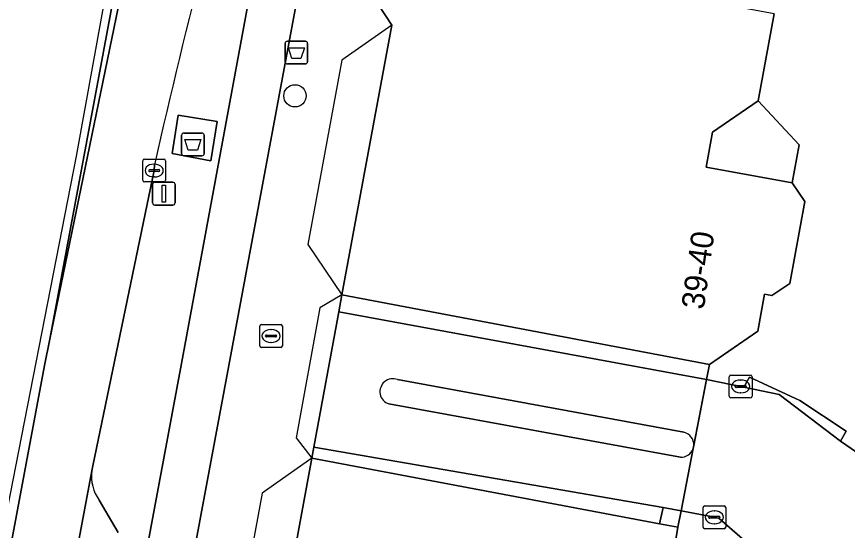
# Model space of a CAD drawing. Extents: x 161838 to 162344, y 381620 to 382160.
# Drawn here: x 161914.31 to 161950.8, y 382018.7 to 382041.26 of the extents above; entities that cross this region are included whole.
import ezdxf

# ---------------------------------------------------------------- set-up
doc = ezdxf.new("R2010")
doc.units = 0
for name, color, linetype in [('IMGEO_Afval_apart_plaats', 7, 'Continuous'), ('IMGEO_Afvalbak', 7, 'Continuous'), ('IMGEO_Berm_open', 7, 'Continuous'), ('IMGEO_Boom', 7, 'Continuous'), ('IMGEO_Brandkraan', 7, 'Continuous'), ('IMGEO_Fietspad_gesloten', 7, 'Continuous'), ('IMGEO_Kolk', 7, 'Continuous'), ('IMGEO_Lichtmast', 7, 'Continuous'), ('IMGEO_OVBaan_gesloten', 7, 'Continuous'), ('IMGEO_Pand', 7, 'Continuous'), ('IMGEO_Pand_nummerreeks', 7, 'Continuous'), ('IMGEO_Pand_overbouw', 7, 'Continuous'), ('IMGEO_Parkeervlak_open', 7, 'Continuous'), ('IMGEO_Rijbaan_lokaal_gesloten', 7, 'Continuous'), ('IMGEO_Rijbaan_lokaal_open', 7, 'Continuous'), ('IMGEO_Verkeerseiland_open', 7, 'Continuous'), ('IMGEO_Voetpad_gesloten', 7, 'Continuous'), ('IMGEO_Voetpad_open', 7, 'Continuous')]:
    doc.layers.add(name, color=color, linetype=linetype)

msp = doc.modelspace()

# ---------------------------------------------------------------- linework, layer by layer
at = {"layer": 'IMGEO_Afval_apart_plaats'}
for p, q in [((161921.659, 382036.149), (161922.449, 382036.149)), ((161922.449, 382036.149), (161921.659, 382036.149)), ((161921.559, 382035.249), (161921.559, 382036.049)), ((161921.559, 382036.049), (161921.559, 382035.249)), ((161922.549, 382036.049), (161922.549, 382035.249)), ((161922.549, 382035.249), (161922.549, 382036.049)), ((161922.449, 382035.149), (161921.659, 382035.149)), ((161921.659, 382035.149), (161922.449, 382035.149))]:
    msp.add_line(p, q, dxfattribs=at)
msp.add_lwpolyline([(161921.702, 382035.863), (161922.406, 382035.863), (161922.257, 382035.393), (161921.851, 382035.393), (161921.702, 382035.863)], dxfattribs=at)
for centre, start, end in [((161921.659, 382036.049), 90, 180), ((161921.659, 382036.049), 90, 180), ((161922.449, 382036.049), 0, 90), ((161922.449, 382036.049), 360, 90), ((161921.659, 382035.249), 180, 270), ((161921.659, 382035.249), 180, 270), ((161922.449, 382035.249), 270, 0), ((161922.449, 382035.249), 270, 0)]:
    msp.add_arc(centre, 0.1, start, end, dxfattribs=at)
at = {"layer": 'IMGEO_Afvalbak'}
for p, q in [((161926.202, 382040.179), (161926.992, 382040.179)), ((161926.992, 382040.179), (161926.202, 382040.179)), ((161926.102, 382039.279), (161926.102, 382040.079)), ((161926.102, 382040.079), (161926.102, 382039.279)), ((161927.092, 382040.079), (161927.092, 382039.279)), ((161927.092, 382039.279), (161927.092, 382040.079)), ((161926.992, 382039.179), (161926.202, 382039.179)), ((161926.202, 382039.179), (161926.992, 382039.179))]:
    msp.add_line(p, q, dxfattribs=at)
msp.add_lwpolyline([(161926.245, 382039.893), (161926.949, 382039.893), (161926.8, 382039.423), (161926.394, 382039.423), (161926.245, 382039.893)], dxfattribs=at)
for centre, start, end in [((161926.202, 382040.079), 90, 180), ((161926.202, 382040.079), 90, 180), ((161926.992, 382040.079), 0, 90), ((161926.992, 382040.079), 360, 90), ((161926.202, 382039.279), 180, 270), ((161926.202, 382039.279), 180, 270), ((161926.992, 382039.279), 270, 0), ((161926.992, 382039.279), 270, 0)]:
    msp.add_arc(centre, 0.1, start, end, dxfattribs=at)
at = {"layer": 'IMGEO_Berm_open'}
for points in [[(161897.858, 381899.101), (161916.698, 382000), (161921.558, 382026.031), (161926.346, 382051.921)], [(161920.367, 382034.753), (161920.351, 382034.502), (161917.651, 382021.542), (161917.608, 382021.312)], [(161917.936, 382020.026), (161918.769, 382018.604)]]:
    msp.add_lwpolyline(points, dxfattribs=at)
msp.add_lwpolyline([(161921.137, 382035.249), (161921.406, 382036.928), (161923.12, 382036.654), (161922.844, 382034.933)], close=True, dxfattribs=at)
for centre, radius, start, end in [((162168.807, 381979.199), 254.575, 163.06875, 167.39526), ((161919.419, 382021.089), 1.825, 172.9882, 215.6288)]:
    msp.add_arc(centre, radius, start, end, dxfattribs=at)
at = {"layer": 'IMGEO_Boom'}
msp.add_circle((161926.534, 382037.78), 0.489, dxfattribs=at)
at = {"layer": 'IMGEO_Brandkraan'}
for p, q in [((161924.987, 382026.812), (161924.987, 382027.664)), ((161925.062, 382027.738), (161925.914, 382027.738)), ((161925.475, 382027.518), (161925.5, 382027.518)), ((161925.988, 382027.664), (161925.988, 382026.812)), ((161925.246, 382027.232), (161925.246, 382027.244)), ((161925.684, 382027.195), (161925.286, 382027.195)), ((161925.289, 382027.281), (161925.687, 382027.281)), ((161925.73, 382027.244), (161925.73, 382027.232)), ((161925.914, 382026.738), (161925.062, 382026.738)), ((161925.498, 382026.958), (161925.473, 382026.958))]:
    msp.add_line(p, q, dxfattribs=at)
for points in [[(161924.987, 382026.812), (161924.987, 382027.664)], [(161925.062, 382027.738), (161925.914, 382027.738)], [(161925.988, 382027.664), (161925.988, 382026.812)], [(161925.914, 382026.738), (161925.062, 382026.738)]]:
    msp.add_lwpolyline(points, dxfattribs=at)
for centre, radius, start, end in [((161925.064, 382027.662), 0.0765, 91.552, 178.448), ((161925.064, 382027.662), 0.0765, 91.552, 178.448), ((161925.912, 382027.662), 0.0765, 1.552, 88.448), ((161925.912, 382027.662), 0.0765, 1.552, 88.448), ((161925.286, 382027.241), 0.0403, 85.8775, 175.7526), ((161925.283, 382027.231), 0.0366, 178.938, 274.7102), ((161925.687, 382027.238), 0.043, 264.8664, 352.4533), ((161925.691, 382027.243), 0.0386, 1.7309, 96.639), ((161925.064, 382026.814), 0.0765, 181.552, 268.448), ((161925.064, 382026.814), 0.0765, 181.552, 268.448), ((161925.912, 382026.814), 0.0765, 271.552, 358.448), ((161925.912, 382026.814), 0.0765, 271.552, 358.448)]:
    msp.add_arc(centre, radius, start, end, dxfattribs=at)
for centre, major_axis, ratio, start_param, end_param in [((161925.474, 382027.238), (-0.387, 0.002), 0.722429, 4.712389, 7.853982), ((161925.499, 382027.238), (-0.39, 0.002), 0.717154, 1.570796, 4.712389)]:
    msp.add_ellipse(centre, major_axis=major_axis, ratio=ratio, start_param=start_param, end_param=end_param, dxfattribs=at)
at = {"layer": 'IMGEO_Fietspad_gesloten'}
for points in [[(161897.095, 381883.929), (161899.866, 381898.705), (161907.39, 381938.834), (161908.427, 381944.469), (161918.786, 382000), (161923.625, 382025.943), (161928.95, 382054.459)], [(161926.346, 382051.921), (161921.558, 382026.031), (161916.698, 382000), (161897.858, 381899.101), (161895.081, 381884.229), (161870.207, 381751.91), (161869.854, 381750), (161864.774, 381722.548), (161862.987, 381712.892), (161857.316, 381682.246)]]:
    msp.add_lwpolyline(points, dxfattribs=at)
at = {"layer": 'IMGEO_Kolk'}
for p, q in [((161919.852, 382034.076), (161919.852, 382034.928)), ((161919.927, 382035.002), (161920.779, 382035.002)), ((161920.34, 382034.782), (161920.365, 382034.782)), ((161920.853, 382034.928), (161920.853, 382034.076)), ((161920.111, 382034.496), (161920.111, 382034.508)), ((161920.549, 382034.459), (161920.151, 382034.459)), ((161920.154, 382034.545), (161920.552, 382034.545)), ((161920.595, 382034.508), (161920.595, 382034.496)), ((161920.779, 382034.002), (161919.927, 382034.002)), ((161920.363, 382034.222), (161920.338, 382034.222)), ((161945.611, 382024.596), (161945.611, 382025.448)), ((161945.686, 382025.522), (161946.538, 382025.522)), ((161946.099, 382025.302), (161946.124, 382025.302)), ((161946.612, 382025.448), (161946.612, 382024.596)), ((161945.87, 382025.016), (161945.87, 382025.028)), ((161946.308, 382024.979), (161945.91, 382024.979)), ((161945.913, 382025.065), (161946.311, 382025.065)), ((161946.354, 382025.028), (161946.354, 382025.016)), ((161946.538, 382024.522), (161945.686, 382024.522)), ((161946.122, 382024.742), (161946.097, 382024.742)), ((161944.534, 382019.778), (161945.386, 382019.778)), ((161944.459, 382018.852), (161944.459, 382019.704)), ((161944.947, 382019.558), (161944.972, 382019.558)), ((161945.46, 382019.704), (161945.46, 382018.852)), ((161944.718, 382019.272), (161944.718, 382019.284)), ((161945.156, 382019.235), (161944.758, 382019.235)), ((161944.761, 382019.321), (161945.159, 382019.321)), ((161944.97, 382018.998), (161944.945, 382018.998)), ((161945.202, 382019.284), (161945.202, 382019.272)), ((161945.386, 382018.778), (161944.534, 382018.778))]:
    msp.add_line(p, q, dxfattribs=at)
for points in [[(161919.852, 382034.076), (161919.852, 382034.928)], [(161919.927, 382035.002), (161920.779, 382035.002)], [(161920.853, 382034.928), (161920.853, 382034.076)], [(161920.779, 382034.002), (161919.927, 382034.002)], [(161945.611, 382024.596), (161945.611, 382025.448)], [(161945.686, 382025.522), (161946.538, 382025.522)], [(161946.612, 382025.448), (161946.612, 382024.596)], [(161946.538, 382024.522), (161945.686, 382024.522)], [(161944.534, 382019.778), (161945.386, 382019.778)], [(161944.459, 382018.852), (161944.459, 382019.704)], [(161945.46, 382019.704), (161945.46, 382018.852)], [(161945.386, 382018.778), (161944.534, 382018.778)]]:
    msp.add_lwpolyline(points, dxfattribs=at)
for centre, radius, start, end in [((161919.929, 382034.926), 0.0765, 91.552, 178.448), ((161919.929, 382034.926), 0.0765, 91.552, 178.448), ((161920.777, 382034.926), 0.0765, 1.552, 88.448), ((161920.777, 382034.926), 0.0765, 1.552, 88.448), ((161920.151, 382034.505), 0.0403, 85.8775, 175.7526), ((161920.148, 382034.495), 0.0366, 178.938, 274.7102), ((161920.552, 382034.502), 0.043, 264.8664, 352.4533), ((161920.556, 382034.507), 0.0386, 1.7309, 96.639), ((161919.929, 382034.078), 0.0765, 181.552, 268.448), ((161919.929, 382034.078), 0.0765, 181.552, 268.448), ((161920.777, 382034.078), 0.0765, 271.552, 358.448), ((161920.777, 382034.078), 0.0765, 271.552, 358.448), ((161945.688, 382025.446), 0.0765, 91.552, 178.448), ((161945.688, 382025.446), 0.0765, 91.552, 178.448), ((161946.536, 382025.446), 0.0765, 1.552, 88.448), ((161946.536, 382025.446), 0.0765, 1.552, 88.448), ((161945.91, 382025.025), 0.0403, 85.8775, 175.7526), ((161945.907, 382025.015), 0.0366, 178.938, 274.7102), ((161946.311, 382025.022), 0.043, 264.8664, 352.4533), ((161946.315, 382025.027), 0.0386, 1.7309, 96.639), ((161945.688, 382024.598), 0.0765, 181.552, 268.448), ((161945.688, 382024.598), 0.0765, 181.552, 268.448), ((161946.536, 382024.598), 0.0765, 271.552, 358.448), ((161946.536, 382024.598), 0.0765, 271.552, 358.448), ((161944.536, 382019.702), 0.0765, 91.552, 178.448), ((161944.536, 382019.702), 0.0765, 91.552, 178.448), ((161945.384, 382019.702), 0.0765, 1.552, 88.448), ((161945.384, 382019.702), 0.0765, 1.552, 88.448), ((161944.758, 382019.281), 0.0403, 85.8775, 175.7526), ((161944.755, 382019.271), 0.0366, 178.938, 274.7102), ((161945.159, 382019.278), 0.043, 264.8664, 352.4533), ((161945.163, 382019.283), 0.0386, 1.7309, 96.639), ((161944.536, 382018.854), 0.0765, 181.552, 268.448), ((161944.536, 382018.854), 0.0765, 181.552, 268.448), ((161945.384, 382018.854), 0.0765, 271.552, 358.448), ((161945.384, 382018.854), 0.0765, 271.552, 358.448)]:
    msp.add_arc(centre, radius, start, end, dxfattribs=at)
for centre, major_axis, ratio, start_param, end_param in [((161920.339, 382034.502), (-0.387, 0.002), 0.722429, 4.712389, 7.853982), ((161920.364, 382034.502), (-0.39, 0.002), 0.717154, 1.570796, 4.712389), ((161946.098, 382025.022), (-0.387, 0.002), 0.722429, 4.712389, 7.853982), ((161946.123, 382025.022), (-0.39, 0.002), 0.717154, 1.570796, 4.712389), ((161944.946, 382019.278), (-0.387, 0.002), 0.722429, 4.712389, 7.853982), ((161944.971, 382019.278), (-0.39, 0.002), 0.717154, 1.570796, 4.712389)]:
    msp.add_ellipse(centre, major_axis=major_axis, ratio=ratio, start_param=start_param, end_param=end_param, dxfattribs=at)
at = {"layer": 'IMGEO_Lichtmast'}
for p, q in [((161920.379, 382033.987), (161921.169, 382033.987)), ((161921.169, 382033.987), (161920.379, 382033.987)), ((161920.279, 382033.087), (161920.279, 382033.887)), ((161920.279, 382033.887), (161920.279, 382033.087)), ((161921.269, 382033.887), (161921.269, 382033.087)), ((161921.269, 382033.087), (161921.269, 382033.887)), ((161921.169, 382032.987), (161920.379, 382032.987)), ((161920.379, 382032.987), (161921.169, 382032.987))]:
    msp.add_line(p, q, dxfattribs=at)
msp.add_lwpolyline([(161920.699, 382033.862), (161920.849, 382033.862), (161920.849, 382033.112), (161920.699, 382033.112), (161920.699, 382033.862)], dxfattribs=at)
for centre, start, end in [((161920.379, 382033.887), 90, 180), ((161920.379, 382033.887), 90, 180), ((161921.169, 382033.887), 0, 90), ((161921.169, 382033.887), 360, 90), ((161920.379, 382033.087), 180, 270), ((161920.379, 382033.087), 180, 270), ((161921.169, 382033.087), 270, 0), ((161921.169, 382033.087), 270, 0)]:
    msp.add_arc(centre, 0.1, start, end, dxfattribs=at)
at = {"layer": 'IMGEO_OVBaan_gesloten'}
for points in [[(161858.651, 381720.96), (161859.425, 381726.158), (161861.132, 381736.231), (161869.606, 381781.344), (161897.211, 381928.16), (161915.531, 382025.949), (161915.767, 382027.092), (161920.812, 382054.098), (161923.657, 382069.694), (161925.944, 382081.248), (161931.886, 382108.929), (161933.831, 382119.131), (161934.302, 382121.796), (161934.443, 382123.117), (161933.101, 382124.399), (161916.93, 382035.129), (161911.481, 382007.357), (161883.773, 381866.122), (161869.795, 381786.79), (161847.814, 381679.325), (161847.327, 381677.629)], [(161934.665, 382107.97), (161936.261, 382116.022), (161937.124, 382120.558), (161934.443, 382123.117), (161934.302, 382121.796), (161933.831, 382119.131), (161931.886, 382108.929), (161925.944, 382081.248), (161923.657, 382069.694), (161920.812, 382054.098), (161915.767, 382027.092), (161918.789, 382041.718)]]:
    msp.add_lwpolyline(points, dxfattribs=at)
at = {"layer": 'IMGEO_Pand'}
for points in [[(161947.585, 382041.384), (161930.72, 382044.512), (161930.212, 382041.772), (161930.789, 382040.881), (161928.594, 382029.042), (161944.746, 382025.983), (161946.866, 382027.443), (161947.166, 382029.069), (161947.489, 382029.01), (161948.271, 382029.548), (161948.935, 382033.148), (161948.379, 382033.955), (161944.593, 382034.653), (161944.875, 382036.179), (161946.88, 382037.56)], [(161944.993, 382011.92), (161945.38, 382014.065), (161944.842, 382014.84), (161941.135, 382015.51), (161941.406, 382017.015), (161943.261, 382018.302), (161943.358, 382018.84), (161942.549, 382018.993), (161927.279, 382021.88), (161925.09, 382010.026), (161924.219, 382009.712), (161923.584, 382006.197), (161940.418, 382003.1), (161941.12, 382006.984), (161943.338, 382008.524), (161943.616, 382010.06), (161943.991, 382009.992), (161944.738, 382010.511)]]:
    msp.add_lwpolyline(points, close=True, dxfattribs=at)
at = {"layer": 'IMGEO_Pand_overbouw'}
for points in [[(161930.789, 382040.881), (161928.602, 382039.344), (161927.104, 382031.261), (161928.594, 382029.042)], [(161946.88, 382037.56), (161944.875, 382036.179), (161944.593, 382034.653), (161948.379, 382033.955), (161948.687, 382035.627)], [(161944.619, 382025.33), (161944.746, 382025.983), (161928.594, 382029.042), (161927.634, 382028.467), (161926.587, 382022.761), (161927.279, 382021.88), (161942.549, 382018.993), (161943.358, 382018.84), (161943.497, 382019.556)], [(161927.279, 382021.88), (161925.094, 382020.343), (161923.598, 382012.245), (161925.09, 382010.026)]]:
    msp.add_lwpolyline(points, close=True, dxfattribs=at)
at = {"layer": 'IMGEO_Parkeervlak_open'}
for points in [[(161917.608, 382021.312), (161913.622, 382000), (161905.11, 381954.479)], [(161918.769, 382018.604), (161917.936, 382020.026)]]:
    msp.add_lwpolyline(points, dxfattribs=at)
msp.add_arc((161919.419, 382021.089), 1.825, 172.9882, 215.6288, dxfattribs=at)
at = {"layer": 'IMGEO_Rijbaan_lokaal_gesloten'}
for points in [[(161918.789, 382041.718), (161915.767, 382027.092), (161915.531, 382025.949), (161897.211, 381928.16), (161869.606, 381781.344), (161861.132, 381736.231), (161859.425, 381726.158), (161858.651, 381720.96)], [(161862.533, 381727.211), (161866.175, 381746.944), (161866.739, 381750), (161866.904, 381750.735), (161870.759, 381771.481), (161871.456, 381775.156), (161894.868, 381899.69), (161899.202, 381922.742), (161901.082, 381932.662), (161902.001, 381937.624), (161903.787, 381947.27), (161904.686, 381952.125), (161905.076, 381954.299), (161905.11, 381954.479), (161913.622, 382000), (161917.608, 382021.312), (161917.651, 382021.542), (161920.351, 382034.502), (161920.367, 382034.753)]]:
    msp.add_lwpolyline(points, dxfattribs=at)
msp.add_arc((162168.807, 381979.199), 254.575, 163.06875, 167.39526, dxfattribs=at)
at = {"layer": 'IMGEO_Rijbaan_lokaal_open'}
for points in [[(161944.055, 382022.425), (161944.619, 382025.33), (161928.457, 382028.297), (161927.367, 382022.359), (161942.704, 382019.707), (161943.497, 382019.556), (161944.031, 382022.305)], [(161931.04, 382025.323), (161943.617, 382023.009)], [(161952.514, 382021.226), (161950.505, 382022.622), (161947.808, 382024.671), (161946.249, 382024.993), (161944.619, 382025.33), (161944.055, 382022.425), (161944.031, 382022.305), (161943.497, 382019.556), (161944.959, 382019.279), (161945.173, 382019.231), (161949.468, 382015.472), (161953.016, 382010.449), (161959.531, 382001.364), (161960.495, 382000), (161966.81, 381991.062), (161968.8, 381988.304), (161965.15, 381985.684), (161964.923, 381986.014), (161964.411, 381985.613)], [(161943.465, 382021.92), (161930.659, 382024.254)]]:
    msp.add_lwpolyline(points, dxfattribs=at)
for centre, radius, start, end in [((161930.837, 382024.793), 0.568, 68.9947, 251.7724), ((161943.504, 382022.468), 0.552, 355.5034, 78.2364), ((161943.505, 382022.47), 0.551, 265.8426, 342.6054)]:
    msp.add_arc(centre, radius, start, end, dxfattribs=at)
at = {"layer": 'IMGEO_Verkeerseiland_open'}
for points in [[(161943.617, 382023.009), (161931.04, 382025.323)], [(161930.659, 382024.254), (161943.465, 382021.92)], [(161944.031, 382022.305), (161944.055, 382022.425)]]:
    msp.add_lwpolyline(points, dxfattribs=at)
for centre, radius, start, end in [((161930.837, 382024.793), 0.568, 68.9947, 251.7724), ((161943.504, 382022.468), 0.552, 355.5034, 78.2364), ((161943.505, 382022.47), 0.551, 265.8426, 342.6054)]:
    msp.add_arc(centre, radius, start, end, dxfattribs=at)
at = {"layer": 'IMGEO_Voetpad_gesloten'}
msp.add_lwpolyline([(161923.12, 382036.654), (161921.406, 382036.928), (161921.137, 382035.249), (161922.844, 382034.933)], close=True, dxfattribs=at)
at = {"layer": 'IMGEO_Voetpad_open'}
for points in [[(161928.95, 382054.459), (161923.625, 382025.943), (161918.786, 382000), (161908.427, 381944.469)], [(161925.09, 382010.026), (161927.279, 382021.88), (161927.367, 382022.359), (161928.457, 382028.297), (161928.594, 382029.042), (161930.789, 382040.881), (161930.212, 382041.772)], [(161947.585, 382041.384), (161946.88, 382037.56), (161948.687, 382035.627), (161948.379, 382033.955), (161948.935, 382033.148), (161948.271, 382029.548), (161947.489, 382029.01), (161947.166, 382029.069), (161946.866, 382027.443), (161944.746, 382025.983), (161944.619, 382025.33), (161946.249, 382024.993), (161946.495, 382025.428), (161948.718, 382024.413), (161950.751, 382023.057), (161950.505, 382022.622), (161952.514, 382021.226)], [(161949.468, 382015.472), (161945.173, 382019.231), (161944.959, 382019.279), (161943.497, 382019.556), (161943.358, 382018.84), (161943.261, 382018.302), (161945.144, 382016.513), (161944.842, 382014.84), (161945.38, 382014.065), (161944.993, 382011.92), (161946.279, 382010.566), (161943.338, 382008.524), (161941.12, 382006.984), (161940.418, 382003.1), (161940.382, 382002.901), (161942.568, 382002.4), (161945.372, 382001.889), (161945.466, 382002.459), (161946.163, 382002.956), (161949.894, 382005.652), (161952.728, 382001.682), (161953.2, 382002.024), (161956.129, 382004.119)]]:
    msp.add_lwpolyline(points, dxfattribs=at)
for points in [[(161946.88, 382037.56), (161944.875, 382036.179), (161944.593, 382034.653), (161948.379, 382033.955), (161948.687, 382035.627)], [(161928.457, 382028.297), (161944.619, 382025.33), (161944.746, 382025.983), (161928.594, 382029.042)], [(161946.249, 382024.993), (161947.808, 382024.671), (161950.505, 382022.622), (161950.751, 382023.057), (161948.718, 382024.413), (161946.495, 382025.428)], [(161927.279, 382021.88), (161942.549, 382018.993), (161942.704, 382019.707), (161927.367, 382022.359)], [(161942.549, 382018.993), (161943.358, 382018.84), (161943.497, 382019.556), (161942.704, 382019.707)]]:
    msp.add_lwpolyline(points, close=True, dxfattribs=at)

# ---------------------------------------------------------------- texts
at = {"layer": 'IMGEO_Pand_nummerreeks'}
msp.add_text('39-40', height=1, rotation=82.1083, dxfattribs=at).set_placement((161944.495, 382028.369))

doc.saveas('drawing.dxf')
